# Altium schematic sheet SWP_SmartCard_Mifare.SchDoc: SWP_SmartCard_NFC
size A3; DocumentNumber: MB1144; Revision: 1.1; SheetNumber: 7; SheetTotal: 25; Project: STM32L476G-eval
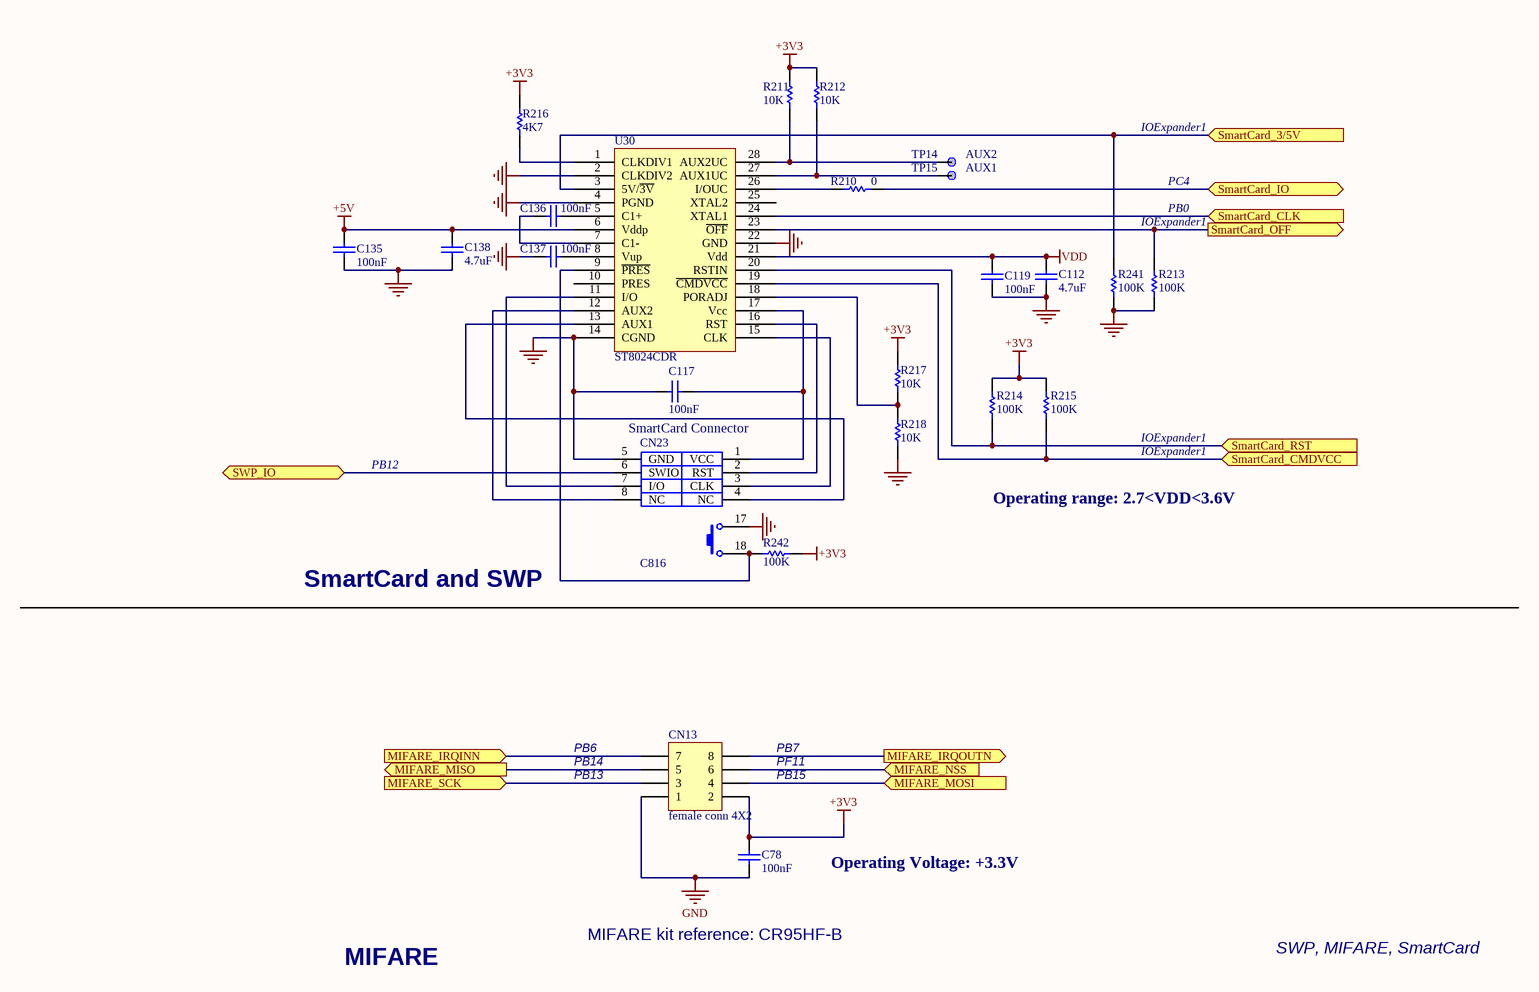
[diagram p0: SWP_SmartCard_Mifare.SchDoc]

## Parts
C78  100nF  [0402C]
C112  4.7uF  [0603C]
C117  100nF  [0402C]
C119  100nF  [0402C]
C135  100nF  [0402C]
C136  100nF  [0402C]
C137  100nF  [0402C]
C138  4.7uF  [0603C]
CN13  female conn 4X2  [HDR_2X4_2R54_N]
CN23  C816  [sam_c816]
R210  0  [0603R]
R211  10K  [0402R]
R212  10K  [0402R]
R213  100K  [0402R]
R214  100K  [0402R]
R215  100K  [0402R]
R216  4K7  [0402R]
R217  10K  [0402R]
R218  10K  [0402R]
R241  100K  [0402R]
R242  100K  [0402R]
TP14  TP Name: AUX2  [TP]  (hidden comment: TP)
TP15  TP Name: AUX1  [TP]  (hidden comment: TP)
U30  ST8024CDR  [SOIC28W_1R27_17R9X10R325]

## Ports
MIFARE_IRQINN (in), MIFARE_IRQOUTN (out), MIFARE_MISO (out), MIFARE_MOSI (in), MIFARE_NSS (in), MIFARE_SCK (in), SmartCard_3/5V (in), SmartCard_CLK (in), SmartCard_CMDVCC (in), SmartCard_IO (bidir), SmartCard_OFF (out), SmartCard_RST (in), SWP_IO (bidir)

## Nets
+3V3: C78.2 CN13.2 R211.1 R212.1 R214.1 R215.1 R216.1 R217.1 R242.1
+5V: C135.1 C138.1 U30.6(Vddp)
GND: C78.1 C112.2 C117.1 C119.2 C135.2 C137.2 C138.2 CN13.1 CN23.5(GND) CN23.17 R213.2 R218.2 R241.2 U30.2(CLKDIV2) U30.4(PGND) U30.14(CGND) U30.22(GND)
VDD: C112.1 C119.1 U30.21(Vdd)
MIFARE_IRQINN: CN13.7 ; port MIFARE_IRQINN
MIFARE_IRQOUTN: CN13.8 ; port MIFARE_IRQOUTN
MIFARE_MISO: CN13.5 ; port MIFARE_MISO
MIFARE_MOSI: CN13.4 ; port MIFARE_MOSI
MIFARE_NSS: CN13.6 ; port MIFARE_NSS
MIFARE_SCK: CN13.3 ; port MIFARE_SCK
SmartCard_3/5V: R241.1 U30.3(5V/~{3V}) ; port SmartCard_3/5V
SmartCard_CLK: U30.24(XTAL1) ; port SmartCard_CLK
SmartCard_CMDVCC: R215.2 U30.19(~{CMDVCC}) ; port SmartCard_CMDVCC
SmartCard_IO: R210.2 ; port SmartCard_IO
SmartCard_OFF: R213.1 U30.23(~{OFF}) ; port SmartCard_OFF
SmartCard_RST: R214.2 U30.20(RSTIN) ; port SmartCard_RST
SWP_IO: CN23.6(SWIO) ; port SWP_IO
NetC117_2: C117.2 CN23.1(VCC) U30.17(Vcc)
NetC136_1: C136.1 U30.7(C1-)
NetC136_2: C136.2 U30.5(C1+)
NetC137_1: C137.1 U30.8(Vup)
NetCN23_2: CN23.2(RST) U30.16(RST)
NetCN23_3: CN23.3(CLK) U30.15(CLK)
NetCN23_4: CN23.4(NC) U30.13(AUX1)
NetCN23_7: CN23.7(I/O) U30.11(I/O)
NetCN23_8: CN23.8(NC) U30.12(AUX2)
NetCN23_18: CN23.18 R242.2 U30.9(~{PRES})
NetR210_1: R210.1 U30.26(I/OUC)
NetR211_2: R211.2 TP14.1 U30.28(AUX2UC)
NetR212_2: R212.2 TP15.1 U30.27(AUX1UC)
NetR216_2: R216.2 U30.1(CLKDIV1)
NetR217_2: R217.2 R218.1 U30.18(PORADJ)

Not connected (* = marked no-connect by the designer): U30 10(PRES) 25(XTAL2)

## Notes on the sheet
- IOExpander1
- PB0
- PC4
- PB12
- (near CN23) SmartCard Connector
- Operating range: 2.7<VDD<3.6V
- SmartCard and SWP
- PB14
- PB6
- PF11
- PB7
- PB13
- PB15
- Operating Voltage: +3.3V
- MIFARE
- MIFARE kit reference: CR95HF-B
- SWP, MIFARE, SmartCard

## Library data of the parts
C78 = CAP: Capacitor; Value: 100pF; Ordered by: Subcon
C112 C138 = Cap: Capacitor; Value: 10nF; Ordered by: Subcon
C117 C119 C135-C137 = CAP: Capacitor; Ordered by: Subcon
CN13 = female conn 4X2: female conn 4X2 4-Pin, Dual row; Ordered by: Subcon
CN23 = Smart_card_CN: Ordered by: Subcon; Comments: Smartcard conenctor
R210-R218 R241 R242 = Res1: Resistor; Value: 1K; Ordered by: Subcon
TP14 TP15 = TP: Ordered by: Subcon
U30 = ST8024CTR: Ordered by: STM; ECCN_US/EU: EAR99/NEC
